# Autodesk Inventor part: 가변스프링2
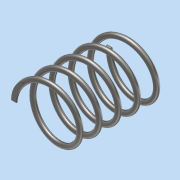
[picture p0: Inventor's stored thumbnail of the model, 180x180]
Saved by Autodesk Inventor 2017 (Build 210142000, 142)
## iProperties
Part Number: 가변스프링2
Material: 강철, 연강
Document SubType Name: Modeling
Designer: MRC
Density: 7.85 g/cm^3
Appearance: 반연마
Mass: 8.42555 g
Surface Area: 21.7274 cm^2
Volume: 1.07332 cm^3
Author: MRC
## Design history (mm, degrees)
sketch "스케치1"
  geometry: L1 (0, 0)-(0, 37.411); L2 (0, 0)-(-11, 0); L3 (0, 37.411)-(-11, 37.411); C1 r 1 at (-11, 0)
  constraints: 6 end point, 2 horizontal, 1 centre point, 1 coincident, 1 vertical
  dimensions: "d0" = 37.4112 distance of L1.start L1.end (derived); "d11" = 11 distance of L1.start L2.end; "d12" = 2 diameter of C1
feature "코일1" sketch "스케치1" pitch "d3" = 10; turns "d5" = 5; dims "d4" = 37.4112 (= d0), "d6" = 0, angle "d7" = 90 deg, angle "d8" = 90 deg, "d9" = 0, "d10" = 0
sketch "스케치2"
  geometry: L1 (37.411, 17.5)-(0, 17.5); L2 (0, 17.5)-(0, -17.5); L3 (0, -17.5)-(37.411, -17.5); L4 (37.411, -17.5)-(37.411, 17.5); 2 further points
  constraints: 8 end point, 2 parallel, 1 coincident, 1 horizontal, 1 midpoint, 1 perpendicular
  dimensions: "d13" = 37.4112 distance of L2.end L3.end (= d0); "d14" = 35 distance of L3.end L1.start
extrude "돌출1" sketch "스케치2" stored distance "d15" = 10; taper "d16" = 0 deg
node "솔리드1"
